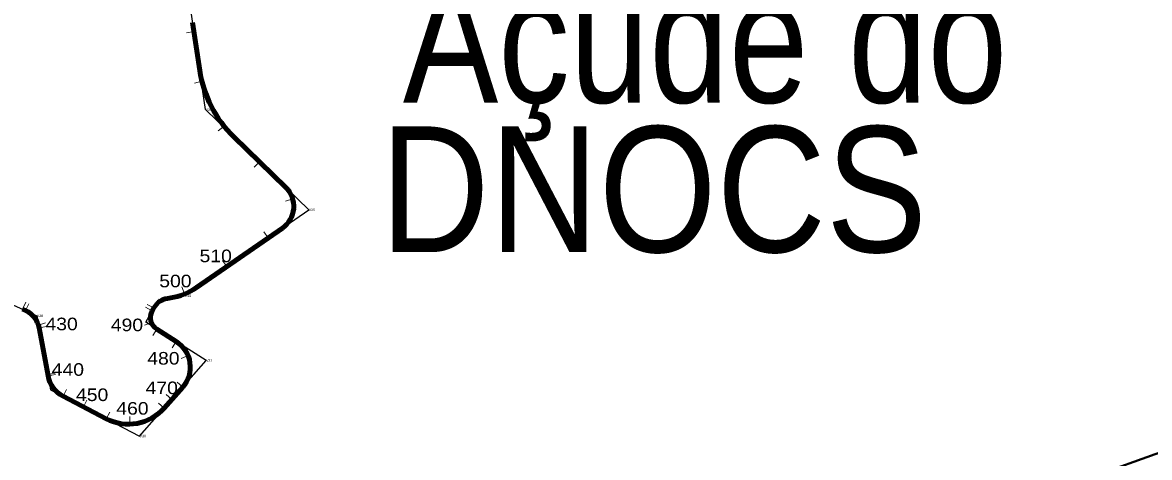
# Model space of a CAD drawing. Extents: x 553962 to 842807, y 8883888 to 9032388.
# Drawn here: x 597590 to 602069, y 8965107 to 8966835 of the extents above; entities that cross this region are included whole.
import ezdxf
from ezdxf.enums import TextEntityAlignment as Align

# ---------------------------------------------------------------- set-up
doc = ezdxf.new("R2010")
doc.units = 0
doc.header["$LTSCALE"] = 20
for name, color, linetype, lineweight in [('12', 7, 'Continuous', 25), ('14', 7, 'Continuous', 13), ('15', 7, 'Continuous', 90), ('26', 7, 'Continuous', 13), ('27', 7, 'Continuous', 13), ('60', 7, 'Continuous', 25), ('9', 7, 'Continuous', 90)]:
    doc.layers.add(name, color=color, linetype=linetype, lineweight=lineweight)
for name, color, linetype in [('13', 7, 'Continuous'), ('50', 7, 'Continuous'), ('61', 7, 'Continuous')]:
    doc.layers.add(name, color=color, linetype=linetype)

msp = doc.modelspace()

# ---------------------------------------------------------------- linework, layer by layer
at = {"layer": '12', "lineweight": 40}
msp.add_lwpolyline([(593118.32, 8961975.46), (594700.75, 8962547.46), (600985.52, 8964722.42), (602091.61, 8965119.89), (602697.14, 8965318.89), (609861.02, 8967928.67)], dxfattribs=at)
at = {"layer": '14'}
for p, q in [((598271.83, 8966799.18), (598242.16, 8966794.75)), ((598294.83, 8966645.16), (598266.43, 8966835.33)), ((598303.45, 8966601.75), (598274.32, 8966594.58)), ((598391.29, 8966423.79), (598367.86, 8966405.06)), ((598636.54, 8966180.01), (598430.43, 8966380.59)), ((598531.96, 8966281.79), (598511.03, 8966260.29)), ((598664.09, 8966134.18), (598635.35, 8966125.6)), ((598281.48, 8965782.15), (598623.04, 8966018.4)), ((598566.47, 8965979.27), (598549.41, 8966003.95)), ((598401.99, 8965865.5), (598384.92, 8965890.18)), ((598234.59, 8965756.65), (598223.35, 8965784.46)), ((597603.06, 8965723.48), (597590.42, 8965696.27)), ((597615.26, 8965717.81), (597602.62, 8965690.6)), ((598166.08, 8965738.84), (598179.22, 8965740.97)), ((597590.42, 8965696.27), (597602.62, 8965690.6)), ((598105.9, 8965689.23), (598079.62, 8965703.7)), ((598112.37, 8965700.98), (598086.09, 8965715.45)), ((598105.9, 8965689.23), (598112.37, 8965700.98)), ((598105.9, 8965689.23), (598112.37, 8965700.98)), ((597653.37, 8965632.52), (597681.94, 8965641.64)), ((598102.64, 8965643.25), (598074.73, 8965632.26)), ((597685.49, 8965627.42), (597656, 8965621.91)), ((597656, 8965621.91), (597691.71, 8965430.98)), ((598108.47, 8965590.98), (598124.57, 8965616.29)), ((598201.44, 8965567.4), (598124.57, 8965616.29)), ((598185.34, 8965542.09), (598201.44, 8965567.4)), ((598247.96, 8965511.93), (598220.32, 8965500.26)), ((597690.76, 8965436.07), (597720.25, 8965441.59)), ((597721.2, 8965436.49), (597691.71, 8965430.98)), ((598204.5, 8965406.56), (598226.98, 8965386.7)), ((597765.47, 8965376.75), (597751.6, 8965350.15)), ((598153.41, 8965303.41), (598226.98, 8965386.7)), ((597751.6, 8965350.15), (597923.19, 8965260.71)), ((597832.03, 8965308.22), (597845.9, 8965334.82)), ((598130.92, 8965323.27), (598153.41, 8965303.41)), ((598183.16, 8965337.09), (598160.67, 8965356.95)), ((597937.05, 8965287.31), (597923.19, 8965260.71)), ((598016.92, 8965239.29), (598016.26, 8965269.28))]:
    msp.add_line(p, q, dxfattribs=at)
for centre, radius, start, end in [((598754.73, 8966713.83), 465, 188.49273, 225.77901), ((598563.31, 8966104.76), 105, 304.67097, 45.779), ((598139.26, 8965987.75), 250, 279.19666, 304.67097), ((598178.07, 8965664.81), 75, 99.19666, 151.1645), ((598178.07, 8965664.81), 75, 99.19666, 151.1645), ((597562.62, 8965604.44), 95, 10.59612, 65.09523), ((598154.08, 8965662.7), 55, 151.16528, 237.54432), ((598154.08, 8965662.7), 55, 151.16528, 200.71427), ((598137.05, 8965466.14), 120, 318.54477, 57.54432), ((597804.75, 8965452.12), 115, 190.59612, 242.46938), ((598011.01, 8965429.19), 190, 242.46938, 318.54477)]:
    msp.add_arc(centre, radius, start, end, dxfattribs=at)
at = {"layer": '15'}
for p, q in [((598294.83, 8966645.16), (598266.43, 8966835.33)), ((598636.54, 8966180.01), (598430.43, 8966380.59)), ((598281.48, 8965782.15), (598623.04, 8966018.4)), ((598166.07, 8965738.84), (598179.22, 8965740.97)), ((597590.42, 8965696.27), (597602.62, 8965690.6)), ((598105.9, 8965689.23), (598112.37, 8965700.98)), ((597656, 8965621.91), (597691.71, 8965430.98)), ((598201.44, 8965567.4), (598124.57, 8965616.29)), ((598153.41, 8965303.41), (598226.98, 8965386.7)), ((597751.6, 8965350.15), (597923.19, 8965260.71))]:
    msp.add_line(p, q, dxfattribs=at)
for centre, radius, start, end in [((598754.73, 8966713.83), 465, 188.49273, 225.77901), ((598563.31, 8966104.76), 105, 304.67097, 45.779), ((598139.26, 8965987.75), 250, 279.19666, 304.67097), ((598178.07, 8965664.8), 75, 99.20758, 151.1645), ((597562.62, 8965604.44), 95, 10.59612, 65.09523), ((598154.08, 8965662.7), 55, 151.1645, 237.54432), ((598137.05, 8965466.14), 120, 318.54477, 57.54432), ((597804.75, 8965452.12), 115, 190.59612, 242.46938), ((598011.01, 8965429.19), 190, 242.46938, 318.54477)]:
    msp.add_arc(centre, radius, start, end, dxfattribs=at)
at = {"layer": '26'}
for p, q in [((598294.83, 8966645.16), (598266.43, 8966835.33)), ((598636.54, 8966180.01), (598430.43, 8966380.59)), ((598281.48, 8965782.15), (598623.04, 8966018.4)), ((598166.07, 8965738.84), (598179.22, 8965740.97)), ((597590.42, 8965696.27), (597602.62, 8965690.6)), ((598105.9, 8965689.23), (598112.37, 8965700.98)), ((597656, 8965621.91), (597691.71, 8965430.98)), ((598201.44, 8965567.4), (598124.57, 8965616.29)), ((598153.41, 8965303.41), (598226.98, 8965386.7)), ((597751.6, 8965350.15), (597923.19, 8965260.71))]:
    msp.add_line(p, q, dxfattribs=at)
for centre, radius, start, end in [((598754.73, 8966713.83), 465, 188.49273, 225.77901), ((598563.31, 8966104.76), 105, 304.67097, 45.779), ((598139.26, 8965987.75), 250, 279.19666, 304.67097), ((598178.07, 8965664.8), 75, 99.20758, 151.1645), ((597562.62, 8965604.44), 95, 10.59612, 65.09523), ((598154.08, 8965662.7), 55, 151.1645, 237.54432), ((598137.05, 8965466.14), 120, 318.54477, 57.54432), ((597804.75, 8965452.12), 115, 190.59612, 242.46938), ((598011.01, 8965429.19), 190, 242.46938, 318.54477)]:
    msp.add_arc(centre, radius, start, end, dxfattribs=at)
at = {"layer": '27'}
for p, q in [((598294.83, 8966645.16), (598266.43, 8966835.33)), ((598636.54, 8966180.01), (598430.43, 8966380.59)), ((598281.48, 8965782.15), (598623.04, 8966018.4)), ((598166.07, 8965738.84), (598179.22, 8965740.97)), ((597590.42, 8965696.27), (597602.62, 8965690.6)), ((598105.9, 8965689.23), (598112.37, 8965700.98)), ((597656, 8965621.91), (597691.71, 8965430.98)), ((598201.44, 8965567.4), (598124.57, 8965616.29)), ((598153.41, 8965303.41), (598226.98, 8965386.7)), ((597751.6, 8965350.15), (597923.19, 8965260.71))]:
    msp.add_line(p, q, dxfattribs=at)
for centre, radius, start, end in [((598754.73, 8966713.83), 465, 188.49273, 225.77901), ((598563.31, 8966104.76), 105, 304.67097, 45.779), ((598139.26, 8965987.75), 250, 279.19666, 304.67097), ((598178.07, 8965664.8), 75, 99.20758, 151.1645), ((597562.62, 8965604.44), 95, 10.59612, 65.09523), ((598154.08, 8965662.7), 55, 151.1645, 237.54432), ((598137.05, 8965466.14), 120, 318.54477, 57.54432), ((597804.75, 8965452.12), 115, 190.59612, 242.46938), ((598011.01, 8965429.19), 190, 242.46938, 318.54477)]:
    msp.add_arc(centre, radius, start, end, dxfattribs=at)
at = {"layer": '60'}
msp.add_lwpolyline([(597535, 8965722), (597647, 8965670), (597702, 8965376), (598055, 8965192), (598320, 8965492), (598081, 8965644), (598130, 8965733), (598235, 8965750), (598728, 8966091), (598318, 8966490), (598252, 8966932)], dxfattribs=at)
at = {"layer": '9'}
msp.add_spline([(592698.54, 8977198.44), (599903.54, 8973292.71), (608459.22, 8968138.19), (612674.79, 8965332.64), (616842.02, 8962096.37), (620004.97, 8958671.19), (621133.98, 8957974.71), (621473.43, 8956805.35), (621586.23, 8956597.47)], degree=3, dxfattribs=at)

# ---------------------------------------------------------------- texts
at = {"layer": '13', "width": 1.15}
for s, p in [('510', (598358.01, 8965882.97)), ('500', (598197.89, 8965783.11)), ('430', (597745.7, 8965612.51)), ('490', (598005.33, 8965608.67)), ('480', (598150.22, 8965476.03)), ('440', (597770.51, 8965431.51)), ('470', (598143.6, 8965358.55)), ('450', (597867.1, 8965331.08)), ('460', (598027.13, 8965277.07))]:
    msp.add_text(s, height=50, dxfattribs=at).set_placement(p, align=Align.CENTER)
at = {"layer": '50'}
for s, width, p in [('Açude do', 0.85, (600302.66, 8966516.8)), ('DNOCS', 0.9, (600097.95, 8965922.86))]:
    msp.add_text(s, height=500, dxfattribs=dict(at, width=width)).set_placement(p, align=Align.CENTER)
at = {"layer": '61'}
for s, width, p in [('V36', 1.05, (598318, 8966485)), ('V35', 1.05, (598728, 8966086)), ('V33', 1.05, (598130, 8965728)), ('V34', 1.05, (598235, 8965745)), ('V28', 1.05, (597647, 8965665)), ('V32', 1.05, (598081, 8965639)), ('V29', 1.05, (597702, 8965371)), ('V30', 1.1, (598055, 8965187))]:
    msp.add_text(s, height=10, dxfattribs=dict(at, width=width)).set_placement(p)
msp.add_text('V31', height=10, dxfattribs=at).set_placement((598320, 8965487))

doc.saveas('drawing.dxf')
